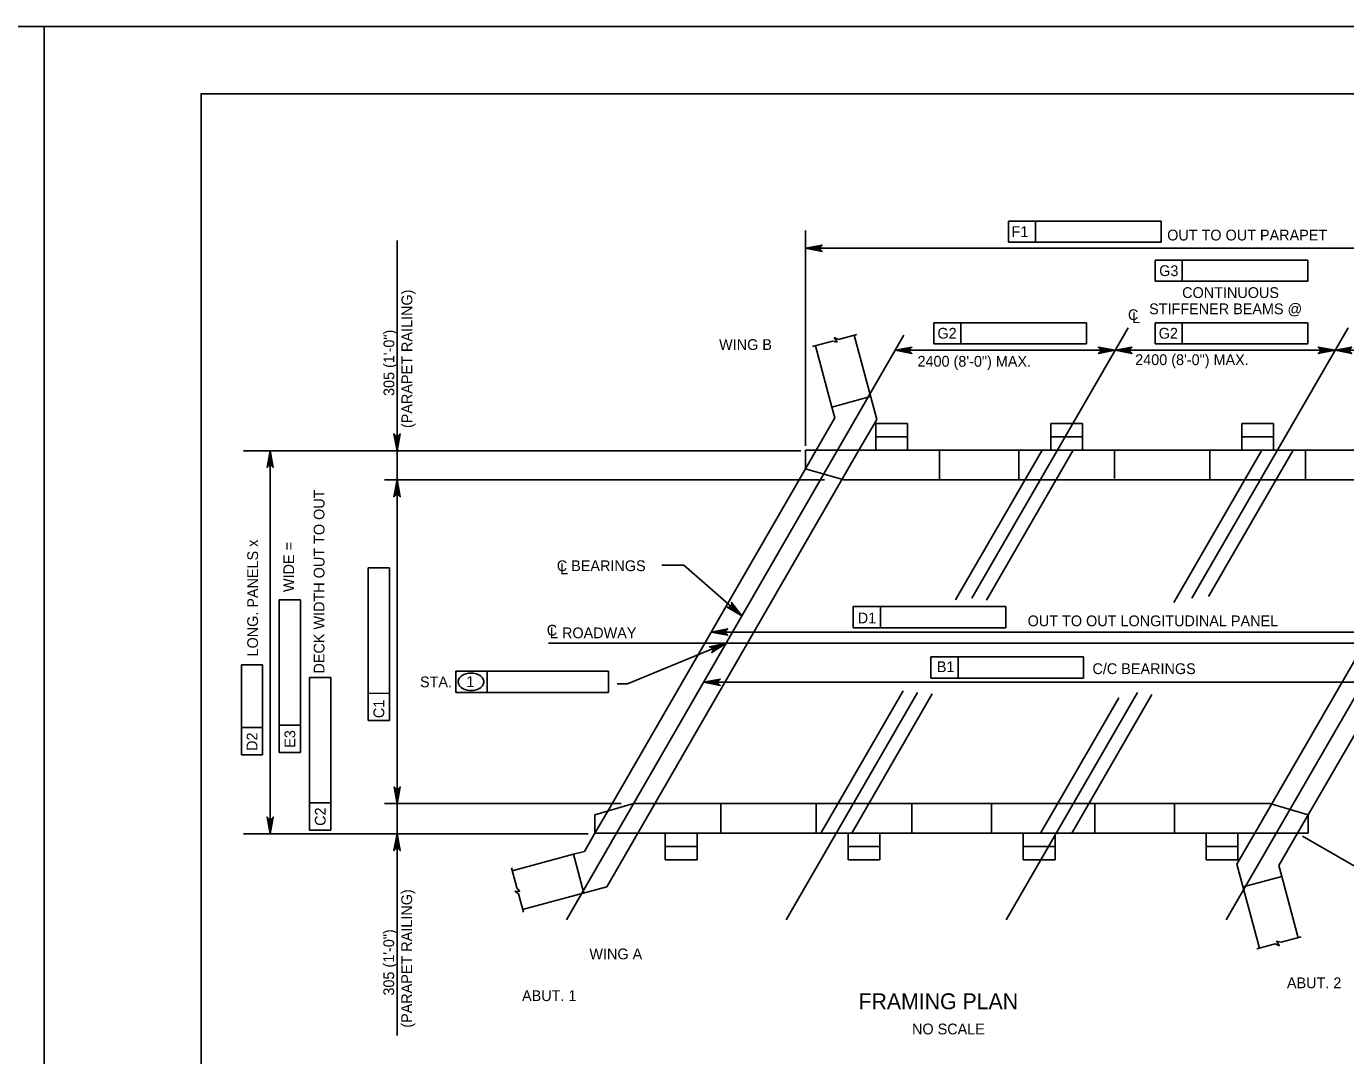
# Model space of a CAD drawing. Extents: x -8 to 75, y -110 to 0.
# Drawn here: x 33.8 to 48.5, y -11.47 to 0 of the extents above; entities that cross this region are included whole.
import ezdxf

# ---------------------------------------------------------------- set-up
doc = ezdxf.new("R2010")
doc.units = 0
for name, color, linetype in [('1', 7, 'Continuous'), ('2', 7, 'Continuous'), ('3', 7, 'Continuous'), ('4', 7, 'Continuous'), ('62', 7, 'Continuous'), ('63', 7, 'Continuous')]:
    doc.layers.add(name, color=color, linetype=linetype)

msp = doc.modelspace()

# ---------------------------------------------------------------- linework, layer by layer
at = {"layer": '1'}
msp.add_lwpolyline([(35.75, -21.25), (67.25, -21.25), (67.25, -0.75), (35.75, -0.75)], close=True, dxfattribs=at)
at = {"layer": '2'}
for p, q in [((43.276, -4.379), (43.025, -3.442)), ((42.776, -4.241), (42.593, -3.558)), ((42.776, -4.241), (43.208, -4.125)), ((42.808, -4.362), (42.776, -4.241)), ((42.601, -4.721), (42.808, -4.362)), ((43.276, -4.379), (43.078, -4.721)), ((43.265, -4.426), (43.265, -4.721)), ((43.62, -4.426), (43.265, -4.426)), ((43.62, -4.426), (43.62, -4.721)), ((45.214, -4.426), (45.214, -4.721)), ((45.569, -4.426), (45.214, -4.426)), ((45.569, -4.426), (45.569, -4.721)), ((47.342, -4.426), (47.342, -4.721)), ((47.342, -4.426), (47.696, -4.426)), ((47.696, -4.426), (47.696, -4.721)), ((40.614, -8.99), (43.078, -4.721)), ((42.482, -4.721), (50.429, -4.721)), ((42.482, -4.928), (42.482, -4.721)), ((42.482, -4.928), (42.601, -4.721)), ((47.486, -8.99), (49.951, -4.721)), ((40.28, -8.742), (42.482, -4.928)), ((42.911, -5.053), (42.482, -4.928)), ((48.083, -8.784), (50.285, -4.97)), ((49.999, -5.053), (42.911, -5.053)), ((40.566, -8.658), (40.136, -8.784)), ((47.654, -8.658), (40.566, -8.658)), ((47.654, -8.658), (48.083, -8.784)), ((40.136, -8.99), (40.28, -8.742)), ((40.136, -8.784), (40.136, -8.99)), ((47.964, -8.99), (48.083, -8.784)), ((48.083, -8.784), (48.083, -8.99)), ((40.02, -9.192), (40.136, -8.99)), ((40.136, -8.99), (48.083, -8.99)), ((40.614, -8.99), (40.269, -9.588)), ((40.92, -9.285), (40.92, -8.99)), ((41.274, -9.285), (41.274, -8.99)), ((42.958, -9.285), (42.958, -8.99)), ((43.312, -9.285), (43.312, -8.99)), ((44.907, -9.285), (44.907, -8.99)), ((45.262, -9.285), (45.262, -8.99)), ((46.945, -9.285), (46.945, -8.99)), ((47.289, -9.332), (47.486, -8.99)), ((47.3, -9.285), (47.3, -8.99)), ((47.756, -9.349), (47.964, -8.99)), ((39.899, -9.224), (39.216, -9.407)), ((40.02, -9.192), (39.899, -9.224)), ((39.899, -9.224), (40.015, -9.656)), ((41.274, -9.285), (40.92, -9.285)), ((43.312, -9.285), (42.958, -9.285)), ((44.907, -9.285), (45.262, -9.285)), ((46.945, -9.285), (47.3, -9.285)), ((47.289, -9.332), (47.54, -10.269)), ((47.756, -9.349), (47.789, -9.47)), ((47.789, -9.47), (47.357, -9.586)), ((47.789, -9.47), (47.972, -10.153)), ((40.269, -9.588), (39.331, -9.839))]:
    msp.add_line(p, q, dxfattribs=at)
at = {"layer": '3'}
for p, q in [((42.56, -3.567), (42.784, -3.507)), ((42.835, -3.518), (42.784, -3.507)), ((42.85, -3.489), (42.802, -3.468)), ((42.802, -3.468), (42.835, -3.518)), ((42.85, -3.489), (43.055, -3.434)), ((43.62, -4.574), (43.265, -4.574)), ((45.569, -4.574), (45.214, -4.574)), ((47.342, -4.574), (47.696, -4.574)), ((43.974, -5.053), (43.974, -4.721)), ((45.117, -4.721), (44.155, -6.387)), ((45.463, -4.721), (44.497, -6.394)), ((44.86, -5.053), (44.86, -4.721)), ((45.924, -4.721), (45.924, -5.038)), ((47.567, -4.721), (46.587, -6.418)), ((47.913, -4.721), (46.971, -6.353)), ((46.987, -4.721), (46.987, -5.053)), ((48.051, -4.721), (48.051, -5.053)), ((43.569, -7.402), (42.652, -8.99)), ((43.895, -7.437), (42.998, -8.99)), ((45.974, -7.479), (45.102, -8.99)), ((46.342, -7.443), (45.448, -8.99)), ((41.54, -8.658), (41.54, -8.99)), ((42.603, -8.658), (42.603, -8.99)), ((43.667, -8.658), (43.667, -8.99)), ((44.553, -8.658), (44.553, -8.99)), ((45.705, -8.658), (45.705, -8.99)), ((46.591, -8.658), (46.591, -8.99)), ((41.274, -9.138), (40.92, -9.138)), ((43.312, -9.138), (42.958, -9.138)), ((44.907, -9.138), (45.262, -9.138)), ((46.945, -9.138), (47.3, -9.138)), ((39.207, -9.374), (39.267, -9.598)), ((39.243, -9.633), (39.302, -9.637)), ((39.285, -9.665), (39.243, -9.633)), ((39.302, -9.637), (39.267, -9.598)), ((39.285, -9.665), (39.34, -9.87)), ((47.715, -10.222), (47.51, -10.277)), ((47.715, -10.222), (47.763, -10.243)), ((47.73, -10.193), (47.781, -10.204)), ((47.763, -10.243), (47.73, -10.193)), ((48.005, -10.144), (47.781, -10.204))]:
    msp.add_line(p, q, dxfattribs=at)
at = {"layer": '4'}
for p, q in [((44.744, -2.169), (46.445, -2.169)), ((44.744, -2.169), (44.744, -2.405)), ((45.046, -2.169), (45.046, -2.405)), ((46.445, -2.169), (46.445, -2.405)), ((42.482, -4.672), (42.482, -2.273)), ((37.933, -2.387), (37.933, -11.243)), ((42.482, -2.472), (50.429, -2.472)), ((44.744, -2.405), (46.445, -2.405)), ((46.376, -2.604), (48.077, -2.604)), ((46.376, -2.604), (46.376, -2.84)), ((46.678, -2.604), (46.678, -2.84)), ((48.077, -2.604), (48.077, -2.84)), ((46.376, -2.84), (48.077, -2.84)), ((43.911, -3.301), (45.612, -3.301)), ((43.911, -3.301), (43.911, -3.537)), ((44.213, -3.301), (44.213, -3.537)), ((46.076, -3.36), (44.336, -6.372)), ((45.612, -3.301), (45.612, -3.537)), ((46.376, -3.301), (48.077, -3.301)), ((46.376, -3.301), (46.376, -3.537)), ((46.678, -3.301), (46.678, -3.537)), ((48.526, -3.36), (46.786, -6.372)), ((48.077, -3.301), (48.077, -3.537)), ((43.579, -3.44), (39.819, -9.954)), ((50.929, -3.44), (47.169, -9.954)), ((43.482, -3.609), (45.932, -3.609)), ((43.911, -3.537), (45.612, -3.537)), ((45.932, -3.609), (48.382, -3.609)), ((46.376, -3.537), (48.077, -3.537)), ((48.382, -3.609), (48.382, -3.609)), ((48.382, -3.609), (50.832, -3.609)), ((42.429, -4.727), (36.222, -4.727)), ((36.519, -8.996), (36.519, -4.727)), ((42.693, -5.053), (37.792, -5.053)), ((40.881, -6.002), (41.126, -6.002)), ((41.126, -6.002), (41.775, -6.566)), ((37.612, -7.733), (37.612, -6.032)), ((37.848, -6.032), (37.612, -6.032)), ((37.848, -7.733), (37.848, -6.032)), ((36.621, -8.089), (36.621, -6.388)), ((36.857, -6.388), (36.621, -6.388)), ((36.857, -8.089), (36.857, -6.388)), ((43.014, -6.464), (44.715, -6.464)), ((43.014, -6.464), (43.014, -6.7)), ((43.317, -6.464), (43.317, -6.7)), ((44.715, -6.464), (44.715, -6.7)), ((41.431, -6.748), (49.258, -6.748)), ((43.014, -6.7), (44.715, -6.7)), ((51.311, -6.872), (39.62, -6.872)), ((41.598, -6.872), (40.499, -7.325)), ((43.88, -7.025), (45.581, -7.025)), ((43.88, -7.025), (43.88, -7.261)), ((44.183, -7.025), (44.183, -7.261)), ((45.581, -7.025), (45.581, -7.261)), ((36.198, -8.115), (36.198, -7.114)), ((36.435, -7.114), (36.198, -7.114)), ((36.435, -8.116), (36.435, -7.114)), ((38.587, -7.184), (40.288, -7.184)), ((38.587, -7.42), (38.587, -7.184)), ((38.937, -7.42), (38.937, -7.184)), ((40.288, -7.184), (40.288, -7.42)), ((36.959, -8.954), (36.959, -7.253)), ((37.195, -7.253), (36.959, -7.253)), ((37.195, -8.954), (37.195, -7.253)), ((40.499, -7.325), (40.385, -7.325)), ((41.347, -7.307), (48.697, -7.307)), ((43.88, -7.261), (45.581, -7.261)), ((37.848, -7.431), (37.612, -7.43)), ((40.288, -7.42), (38.587, -7.42)), ((43.73, -7.422), (42.268, -9.954)), ((46.18, -7.422), (44.718, -9.954)), ((36.857, -7.787), (36.621, -7.786)), ((37.612, -7.733), (37.848, -7.733)), ((36.435, -7.813), (36.198, -7.813)), ((36.198, -8.115), (36.435, -8.116)), ((36.621, -8.089), (36.857, -8.089)), ((37.195, -8.651), (36.959, -8.651)), ((40.43, -8.658), (37.792, -8.658)), ((36.959, -8.954), (37.195, -8.954)), ((40.06, -8.996), (36.222, -8.996)), ((48.018, -9.021), (50.984, -10.734))]:
    msp.add_line(p, q, dxfattribs=at)
for points in [[(42.482, -2.472), (42.668, -2.437), (42.654, -2.447), (42.646, -2.46), (42.644, -2.472), (42.646, -2.485), (42.654, -2.497), (42.668, -2.507), (42.482, -2.472), (42.654, -2.497), (42.646, -2.485), (42.482, -2.472), (42.644, -2.472), (42.646, -2.46), (42.482, -2.472), (42.654, -2.447)], [(43.482, -3.609), (43.668, -3.574), (43.654, -3.584), (43.646, -3.597), (43.644, -3.609), (43.646, -3.622), (43.654, -3.634), (43.668, -3.644), (43.482, -3.609), (43.654, -3.634), (43.646, -3.622), (43.482, -3.609), (43.644, -3.609), (43.646, -3.597), (43.482, -3.609), (43.654, -3.584)], [(45.932, -3.609), (45.745, -3.644), (45.76, -3.634), (45.767, -3.622), (45.769, -3.609), (45.767, -3.597), (45.76, -3.584), (45.745, -3.574), (45.932, -3.609), (45.76, -3.584), (45.767, -3.597), (45.932, -3.609), (45.769, -3.609), (45.767, -3.622), (45.932, -3.609), (45.76, -3.634)], [(45.932, -3.609), (46.118, -3.574), (46.104, -3.584), (46.096, -3.597), (46.094, -3.609), (46.096, -3.622), (46.104, -3.634), (46.118, -3.644), (45.932, -3.609), (46.104, -3.634), (46.096, -3.622), (45.932, -3.609), (46.094, -3.609), (46.096, -3.597), (45.932, -3.609), (46.104, -3.584)], [(48.382, -3.609), (48.195, -3.644), (48.21, -3.634), (48.217, -3.622), (48.219, -3.609), (48.217, -3.597), (48.21, -3.584), (48.195, -3.574), (48.382, -3.609), (48.21, -3.584), (48.217, -3.597), (48.382, -3.609), (48.219, -3.609), (48.217, -3.622), (48.382, -3.609), (48.21, -3.634)], [(48.382, -3.609), (48.568, -3.574), (48.554, -3.584), (48.547, -3.597), (48.544, -3.609), (48.547, -3.622), (48.554, -3.634), (48.568, -3.644), (48.382, -3.609), (48.554, -3.634), (48.547, -3.622), (48.382, -3.609), (48.544, -3.609), (48.547, -3.597), (48.382, -3.609), (48.554, -3.584)], [(37.933, -4.727), (37.898, -4.541), (37.908, -4.555), (37.92, -4.562), (37.933, -4.565), (37.945, -4.562), (37.958, -4.555), (37.968, -4.541), (37.933, -4.727), (37.958, -4.555), (37.945, -4.562), (37.933, -4.727), (37.933, -4.565), (37.92, -4.562), (37.933, -4.727), (37.908, -4.555)], [(36.519, -4.727), (36.554, -4.913), (36.544, -4.899), (36.531, -4.892), (36.519, -4.89), (36.506, -4.892), (36.494, -4.899), (36.484, -4.913), (36.519, -4.727), (36.494, -4.899), (36.506, -4.892), (36.519, -4.727), (36.519, -4.89), (36.531, -4.892), (36.519, -4.727), (36.544, -4.899)], [(37.933, -5.053), (37.968, -5.24), (37.958, -5.225), (37.945, -5.218), (37.933, -5.216), (37.92, -5.218), (37.908, -5.225), (37.898, -5.24), (37.933, -5.053), (37.908, -5.225), (37.92, -5.218), (37.933, -5.053), (37.933, -5.216), (37.945, -5.218), (37.933, -5.053), (37.958, -5.225)], [(41.775, -6.566), (41.611, -6.47), (41.629, -6.472), (41.642, -6.467), (41.652, -6.459), (41.659, -6.448), (41.661, -6.434), (41.657, -6.417), (41.775, -6.566), (41.661, -6.434), (41.659, -6.448), (41.775, -6.566), (41.652, -6.459), (41.642, -6.467), (41.775, -6.566), (41.629, -6.472)], [(41.431, -6.748), (41.617, -6.713), (41.603, -6.723), (41.596, -6.735), (41.594, -6.748), (41.596, -6.76), (41.603, -6.773), (41.617, -6.783), (41.431, -6.748), (41.603, -6.773), (41.596, -6.76), (41.431, -6.748), (41.594, -6.748), (41.596, -6.735), (41.431, -6.748), (41.603, -6.723)], [(41.598, -6.872), (41.439, -6.976), (41.448, -6.961), (41.45, -6.946), (41.448, -6.934), (41.441, -6.923), (41.429, -6.915), (41.412, -6.911), (41.598, -6.872), (41.429, -6.915), (41.441, -6.923), (41.598, -6.872), (41.448, -6.934), (41.45, -6.946), (41.598, -6.872), (41.448, -6.961)], [(41.347, -7.307), (41.533, -7.272), (41.519, -7.282), (41.511, -7.295), (41.509, -7.307), (41.511, -7.32), (41.519, -7.332), (41.533, -7.342), (41.347, -7.307), (41.519, -7.332), (41.511, -7.32), (41.347, -7.307), (41.509, -7.307), (41.511, -7.295), (41.347, -7.307), (41.519, -7.282)], [(37.934, -8.66), (37.899, -8.474), (37.909, -8.488), (37.922, -8.495), (37.934, -8.498), (37.947, -8.495), (37.959, -8.488), (37.969, -8.474), (37.934, -8.66), (37.959, -8.488), (37.947, -8.495), (37.934, -8.66), (37.934, -8.498), (37.922, -8.495), (37.934, -8.66), (37.909, -8.488)], [(36.519, -8.996), (36.484, -8.81), (36.494, -8.824), (36.506, -8.832), (36.519, -8.834), (36.531, -8.832), (36.544, -8.824), (36.554, -8.81), (36.519, -8.996), (36.544, -8.824), (36.531, -8.832), (36.519, -8.996), (36.519, -8.834), (36.506, -8.832), (36.519, -8.996), (36.494, -8.824)], [(37.933, -8.996), (37.968, -9.183), (37.958, -9.168), (37.945, -9.161), (37.933, -9.159), (37.92, -9.161), (37.908, -9.168), (37.898, -9.183), (37.933, -8.996), (37.908, -9.168), (37.92, -9.161), (37.933, -8.996), (37.933, -9.159), (37.945, -9.161), (37.933, -8.996), (37.958, -9.168)]]:
    msp.add_lwpolyline(points, dxfattribs=at)
for points in [[(43.595, -3.59), (43.595, -3.628), (43.482, -3.609)], [(45.818, -3.59), (45.818, -3.628), (45.932, -3.609)], [(46.045, -3.59), (46.045, -3.628), (45.932, -3.609)], [(48.268, -3.59), (48.268, -3.628), (48.382, -3.609)], [(48.495, -3.59), (48.495, -3.628), (48.382, -3.609)], [(36.5, -4.84), (36.538, -4.84), (36.519, -4.727)], [(41.673, -6.503), (41.699, -6.473), (41.775, -6.566)], [(41.549, -6.728), (41.549, -6.768), (41.431, -6.748)], [(41.486, -6.898), (41.5, -6.933), (41.598, -6.872)], [(41.465, -7.287), (41.465, -7.327), (41.347, -7.307)], [(36.5, -8.883), (36.538, -8.883), (36.519, -8.996)]]:
    msp.add_lwpolyline(points, close=True, dxfattribs=at)
for centre, radius, start, end in [((38.68, -7.302), 0.067, 148.5507, 180), ((38.68, -7.302), 0.067, 180, 211.4493), ((38.717, -7.325), 0.11, 124.109, 148.5507), ((38.717, -7.28), 0.11, 211.4493, 235.891), ((38.741, -7.36), 0.153, 105.6708, 124.109), ((38.756, -7.416), 0.211, 90, 105.6708), ((38.756, -7.416), 0.211, 74.3292, 90), ((38.772, -7.36), 0.153, 55.891, 74.3292), ((38.796, -7.325), 0.11, 31.4493, 55.891), ((38.796, -7.28), 0.11, 304.109, 328.5507), ((38.832, -7.302), 0.067, 0, 31.4493), ((38.832, -7.302), 0.067, 328.5507, 0), ((38.741, -7.245), 0.153, 235.891, 254.3292), ((38.756, -7.189), 0.211, 254.3292, 270), ((38.756, -7.189), 0.211, 270, 285.6708), ((38.772, -7.245), 0.153, 285.6708, 304.109)]:
    msp.add_arc(centre, radius, start, end, dxfattribs=at)
at = {"layer": '62'}
msp.add_line((34, 0), (34, 0), dxfattribs=at)
at = {"layer": '63'}
for points in [[(0, -22), (34, -22), (34, 0), (0, 0)], [(34, -22), (68, -22), (68, 0), (34, 0)]]:
    msp.add_lwpolyline(points, close=True, dxfattribs=at)

# ---------------------------------------------------------------- texts
at = {"layer": '4'}
for s, rotation, p in [('F1', 359.9382, (44.777, -2.347)), ('G3', 359.9382, (46.422, -2.782)), ('(PARAPET RAILING)', 90, (38.102, -4.475)), ('G2', 359.9382, (43.952, -3.479)), ('G2', 359.9382, (46.417, -3.479)), ('305 (1\'-0")', 90, (37.902, -4.118)), ('2400 (8\'-0") MAX.', 359.9382, (43.73, -3.791)), ('2400 (8\'-0") MAX.', 359.9382, (46.155, -3.773)), ('DECK WIDTH OUT TO OUT', 90, (37.124, -7.21)), ('LONG. PANELS x', 90, (36.384, -7.02)), ('WIDE =', 90, (36.786, -6.302)), ('D1', 359.9382, (43.065, -6.651)), ('B1', 359.9382, (43.945, -7.194)), ('C1', 89.9382, (37.79, -7.707)), ('D2', 89.9382, (36.377, -8.072)), ('E3', 89.9382, (36.799, -8.037)), ('C2', 89.9382, (37.137, -8.907)), ('(PARAPET RAILING)', 90, (38.1, -11.156)), ('305 (1\'-0")', 90, (37.9, -10.798))]:
    msp.add_text(s, height=0.12, rotation=rotation, dxfattribs=at).set_placement(p)
for s, height, p in [('OUT TO OUT PARAPET ', 0.12, (46.511, -2.385)), ('CONTINUOUS', 0.12, (46.678, -3.026)), ('STIFFENER BEAMS @', 0.12, (46.31, -3.207)), ('C', 0.12, (46.074, -3.272)), ('L', 0.12, (46.122, -3.306)), ('WING B', 0.12, (41.52, -3.605)), ('C BEARINGS', 0.12, (39.712, -6.069)), ('L', 0.12, (39.751, -6.103)), ('OUT TO OUT LONGITUDINAL PANEL', 0.12, (44.957, -6.683)), ('C', 0.12, (39.6, -6.787)), ('L ROADWAY', 0.12, (39.636, -6.817)), ('C/C BEARINGS', 0.12, (45.679, -7.216)), ('STA.', 0.12, (38.188, -7.363)), ('1', 0.12, (38.704, -7.361)), ('WING A', 0.12, (40.075, -10.394)), ('ABUT. 2', 0.12, (47.845, -10.716)), ('ABUT. 1', 0.12, (39.325, -10.859)), ('FRAMING PLAN', 0.17717, (43.073, -10.95)), ('NO SCALE', 0.12, (43.669, -11.23))]:
    msp.add_text(s, height=height, dxfattribs=at).set_placement(p)

doc.saveas('drawing.dxf')
